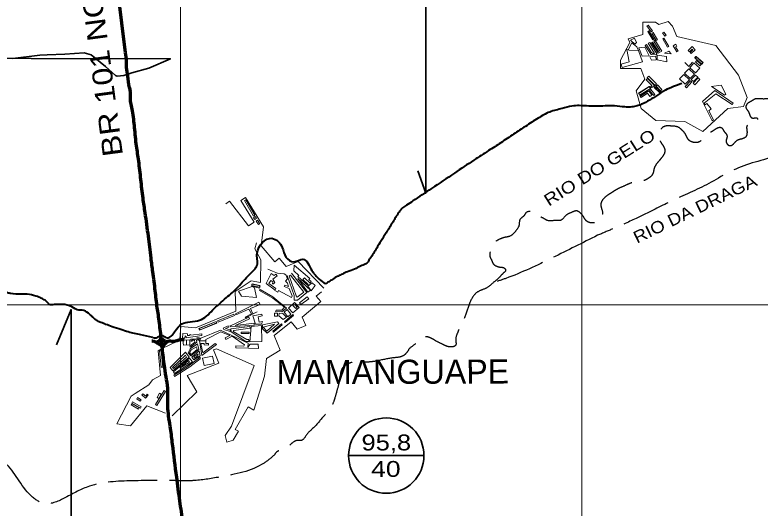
# Model space of a CAD drawing. Extents: x 0 to 1682, y 0 to 1188.
# Drawn here: x 1499.4 to 1617.7, y 586 to 664.3 of the extents above; entities that cross this region are included whole.
import ezdxf
from ezdxf.enums import TextEntityAlignment as Align

# ---------------------------------------------------------------- set-up
doc = ezdxf.new("R2010")
doc.units = 0
doc.header["$LTSCALE"] = 1.3
doc.linetypes.add('DOT_DASHED', pattern=[7.7, 5, -1.2, 0.3, -1.2])
doc.linetypes.add('LONG_DASHED', pattern=[7.5, 6, -1.5])
for name, color, linetype, lineweight in [('1', 7, 'DOT_DASHED', 13), ('3', 7, 'Continuous', 35), ('4', 7, 'Continuous', 13), ('5', 7, 'LONG_DASHED', 25), ('6', 7, 'Continuous', 40), ('63', 7, 'Continuous', 25), ('8', 7, 'Continuous', 35), ('9', 7, 'Continuous', 40)]:
    doc.layers.add(name, color=color, linetype=linetype, lineweight=lineweight)

msp = doc.modelspace()

# ---------------------------------------------------------------- linework, layer by layer
at = {"layer": '1', "linetype": 'Continuous'}
for p, q in [((1612.301, 651.769), (1612.093, 651.595)), ((1525.103, 612.432), (1523.013, 611.428)), ((1526.676, 611.907), (1526.165, 611.897)), ((1526.676, 611.898), (1526.666, 612.683))]:
    msp.add_line(p, q, dxfattribs=at)
for points in [[(1615.089, 649.802), (1612.587, 649.456), (1608.64, 645.821), (1605.76, 647.404), (1601.16, 647.559), (1598.854, 649.449), (1598.067, 652.257), (1599.415, 654.123), (1598.801, 655.815), (1595.554, 655.839), (1595.563, 657.125), (1597.064, 659.941), (1596.791, 660.515), (1599.123, 661.2), (1599.117, 663.197), (1601.115, 663.203), (1601.655, 662.799), (1603.142, 663.311), (1603.821, 662.534), (1603.821, 662.534), (1604.536, 660.911), (1610.696, 659.473), (1614.33, 654.743), (1615.66, 651.192)], [(1599.739, 662.576), (1600.421, 661.632), (1600.629, 661.782), (1599.947, 662.726)], [(1599.904, 661.72), (1600.706, 660.392), (1600.875, 660.494), (1600.074, 661.822)], [(1600.54, 661.441), (1601.223, 660.245), (1601.43, 660.364), (1600.747, 661.559)], [(1602.223, 661.46), (1602.594, 660.944), (1602.797, 661.09), (1602.427, 661.607)], [(1597.133, 660.307), (1597.782, 660.62), (1598.094, 659.971), (1597.858, 659.689)], [(1601.045, 660.363), (1600.839, 660.185), (1601.818, 658.636), (1601.604, 658.501), (1600.653, 660.005), (1600.506, 659.912), (1601.567, 658.234), (1602.11, 658.577)], [(1602.27, 660.529), (1603.057, 659.187), (1603.249, 659.3), (1602.463, 660.642)], [(1598.48, 659.084), (1599.03, 657.785), (1600.137, 657.848), (1599.41, 659.205)], [(1601.318, 658.176), (1600.205, 659.976), (1599.955, 659.822), (1600.958, 658.199), (1600.683, 658.204), (1600.46, 658.41), (1599.689, 659.62), (1599.482, 659.488), (1600.419, 658.018), (1601.244, 657.984)], [(1604.516, 658.475), (1603.94, 659.399), (1604.357, 659.659), (1604.528, 659.385), (1604.311, 659.25), (1604.725, 658.585)], [(1606.809, 658.219), (1606.644, 658.383), (1607.053, 658.794), (1606.939, 658.907), (1606.518, 658.484), (1606.319, 658.682), (1606.941, 659.308), (1607.446, 658.805)], [(1595.832, 655.973), (1595.682, 656.534), (1596.928, 656.865), (1596.576, 658.827), (1596.96, 658.725), (1598.422, 658.656), (1599.077, 656.884)], [(1602.931, 656.895), (1601.409, 657.216), (1601.392, 657.925), (1602.884, 657.723)], [(1603.621, 658.124), (1602.572, 658.269), (1603.236, 658.596)], [(1600.212, 657.671), (1600.464, 657.139), (1601.232, 657.215), (1601.176, 657.781)], [(1607.483, 655.119), (1606.557, 655.947), (1607.235, 656.705), (1608.161, 655.877)], [(1608.488, 656.524), (1607.358, 657.516), (1607.56, 657.745), (1608.69, 656.754)], [(1608.446, 656.511), (1607.366, 657.554), (1607.554, 657.75), (1608.634, 656.706)], [(1607.478, 656.89), (1608.176, 656.226), (1608.371, 656.43), (1607.672, 657.094)], [(1605.753, 655.067), (1606.64, 654.223), (1607.322, 654.94), (1606.435, 655.784)], [(1601.306, 653.368), (1600.054, 654.613), (1599.812, 654.37), (1601.063, 653.124)], [(1606.529, 654.014), (1605.603, 654.892), (1604.936, 654.188), (1605.861, 653.31)], [(1607.15, 653.739), (1607.822, 654.423), (1607.466, 654.772), (1606.795, 654.088)], [(1608.19, 654.071), (1607.355, 653.246), (1607.09, 653.515), (1607.925, 654.34)], [(1600.536, 652.824), (1600.388, 652.971), (1600.535, 653.119), (1599.625, 654.025), (1599.838, 654.24), (1600.956, 653.128)], [(1601.215, 653.003), (1601.926, 652.281), (1602.157, 652.508), (1601.446, 653.231)], [(1606.666, 653.877), (1605.833, 652.958), (1606.055, 652.757), (1606.888, 653.676)], [(1598.432, 651.901), (1600.128, 652.982), (1600.33, 652.666), (1598.608, 651.568)], [(1598.457, 651.827), (1600.181, 652.97), (1600.367, 652.69), (1598.643, 651.547)], [(1598.858, 651.193), (1599.875, 651.89), (1600.242, 651.356), (1600.557, 651.572), (1600.061, 652.294), (1598.705, 651.363)], [(1600.183, 652.29), (1600.835, 651.509), (1601.043, 651.682), (1600.391, 652.464)], [(1601.808, 651.955), (1600.905, 652.795), (1601.04, 652.94), (1601.943, 652.1)], [(1536.092, 634.97), (1537.501, 632.513), (1537.278, 632.385), (1535.869, 634.842)], [(1537.766, 632.026), (1537.562, 632.289), (1537.299, 632.085), (1537.502, 631.822)], [(1537.93, 631.721), (1538.297, 631.153), (1538.089, 631.018), (1537.721, 631.586)], [(1546.225, 622.472), (1543.741, 624.579), (1543.682, 623.684), (1544.497, 622.934), (1544.341, 622.764), (1545.844, 621.381), (1545.983, 621.532), (1545.138, 622.31), (1545.372, 622.565), (1546.268, 621.74), (1546.471, 621.96), (1546.098, 622.304)], [(1544.06, 619.699), (1542.933, 622.889), (1543.182, 622.977), (1545.277, 620.272), (1544.253, 619.479)], [(1544.356, 622.466), (1545.947, 620.315), (1546.332, 620.6)], [(1538.292, 621.324), (1537.097, 621.602), (1537.039, 621.352), (1538.234, 621.074)], [(1537.05, 621.253), (1537.05, 621.554), (1538.331, 621.322), (1538.263, 620.95)], [(1546.613, 621.761), (1545.904, 621.23), (1546.435, 620.521), (1547.082, 621.335)], [(1537.775, 619.463), (1535.371, 619.65), (1534.923, 620.464), (1537.091, 621.169), (1537.479, 620.956)], [(1540.877, 617.419), (1541.792, 617.422), (1542.235, 617.894), (1540.388, 619.327), (1538.268, 620.55), (1538.352, 620.697), (1540.384, 619.525), (1542.549, 617.738), (1541.819, 617.186), (1540.773, 617.196)], [(1544.795, 618.319), (1544.591, 618.582), (1545.836, 619.545), (1546.081, 619.229)], [(1535.981, 616.306), (1535.981, 616.306), (1536.959, 616.871), (1536.537, 617.601), (1534.516, 616.694), (1534.446, 616.85), (1538.169, 618.68), (1538.349, 618.313), (1536.839, 617.721), (1537.176, 616.861), (1537.901, 617.146), (1536.02, 616.188)], [(1544.558, 617.853), (1543.799, 618.671), (1542.834, 617.775), (1543.554, 617)], [(1544.025, 617.678), (1543.528, 618.161), (1543.875, 618.311), (1544.248, 617.927)], [(1531.686, 615.517), (1534.257, 616.579), (1534.167, 616.796), (1531.596, 615.734)], [(1538.558, 615.214), (1537.604, 615.212), (1537.208, 616.518), (1538.632, 616.81), (1538.691, 616.519), (1538.028, 616.383), (1538.205, 615.522), (1538.71, 615.626)], [(1540.617, 616.475), (1540.616, 616.96), (1541.1, 616.961), (1541.101, 616.477)], [(1542.021, 615.933), (1541.336, 616.552), (1541.372, 616.962), (1541.945, 616.912), (1542.516, 616.344)], [(1542.727, 616.395), (1542.141, 617.113), (1542.639, 617.519), (1543.22, 616.805)], [(1542.345, 615.45), (1543.669, 616.596), (1543.545, 616.739), (1542.221, 615.592)], [(1531.476, 615.376), (1528.741, 614.267), (1528.638, 614.521), (1531.373, 615.63)], [(1531.438, 615.395), (1528.803, 614.314), (1528.716, 614.527), (1531.35, 615.607)], [(1533.56, 614.914), (1536.551, 616.305), (1536.671, 616.048), (1534.407, 614.996), (1537.42, 615.371), (1537.38, 615.066), (1533.622, 614.759), (1533.602, 615.012)], [(1538.725, 614.445), (1539.484, 613.789), (1541.34, 615.297), (1541.124, 615.564), (1538.735, 615.103)], [(1538.062, 612.022), (1536.775, 612.018), (1536.402, 611.549), (1536.447, 612.181), (1532.041, 614.277), (1528.932, 613.002), (1528.652, 612.556), (1529.706, 612.513), (1529.706, 612.513), (1529.705, 612.794), (1529.705, 612.794), (1532.135, 613.973), (1533.564, 613.414), (1532.793, 613.014), (1532.914, 612.782), (1533.906, 613.297), (1535.886, 611.945), (1535.736, 611.726), (1534.505, 611.754), (1534.499, 611.448), (1536.476, 611.403), (1538.108, 611.367)], [(1533.585, 614.018), (1533.585, 614.29), (1532.867, 614.521), (1533.37, 614.755), (1533.281, 614.945), (1532.506, 614.584), (1532.611, 614.36)], [(1536.536, 612.456), (1536.535, 612.766), (1536.224, 612.765), (1534.089, 614.059), (1534.19, 614.226), (1536.743, 614.571), (1536.703, 614.862), (1533.704, 614.456), (1533.768, 613.981), (1536.071, 612.435)], [(1536.728, 612.376), (1536.944, 614.818), (1538.589, 615.006), (1538.596, 612.463)], [(1539.396, 614.112), (1538.811, 614.743), (1540.621, 615.184)], [(1540.599, 614.053), (1541.849, 615.113), (1541.718, 615.268), (1540.341, 614.101), (1540.494, 613.921)], [(1529.103, 613.407), (1529.102, 613.655), (1527.331, 613.443), (1527.316, 613.562), (1527.114, 613.538), (1527.127, 613.426), (1526.835, 613.391), (1526.8, 613.683), (1526.069, 613.72), (1526.032, 612.989), (1526.418, 612.97), (1526.438, 613.357), (1526.614, 613.194), (1526.615, 613.062)], [(1528.438, 612.613), (1528.28, 613.058), (1528.725, 613.06)], [(1535.318, 613.935), (1536.605, 613.939), (1536.606, 613.705), (1535.319, 613.701)], [(1526.165, 611.897), (1526.08, 612.664), (1527.185, 612.7), (1527.211, 611.899)], [(1528.629, 611.189), (1528.418, 612.061), (1527.241, 611.283), (1526.899, 610.655), (1527.368, 610.152)], [(1527.373, 612.511), (1527.372, 612.821), (1528.167, 612.824), (1528.303, 612.328), (1527.303, 611.559), (1527.174, 611.727), (1527.967, 612.336), (1527.93, 612.647), (1527.566, 612.647), (1527.566, 612.495), (1527.357, 612.495)], [(1531.415, 611.97), (1531.217, 612.151), (1529.268, 610.652), (1528.95, 612.153), (1529.469, 612.13), (1529.459, 611.899), (1530.128, 611.87), (1530.14, 612.139), (1529.734, 612.158), (1529.752, 612.563), (1528.697, 612.61), (1529.096, 610.231)], [(1522.621, 608.368), (1522.38, 610.961), (1522.638, 610.985), (1522.879, 608.392)], [(1524.477, 607.771), (1524.082, 608.311), (1526.494, 610.74), (1527.061, 609.979)], [(1528.371, 611.176), (1527.391, 610.411), (1527.143, 610.728), (1527.377, 611.148), (1528.247, 611.63)], [(1528.804, 610.169), (1528.654, 610.967), (1527.479, 609.981), (1527.845, 609.544)], [(1524.574, 608.153), (1524.438, 608.349), (1526.508, 610.297), (1526.644, 609.966)], [(1527.148, 609.808), (1527.591, 609.207), (1524.761, 607.367), (1524.596, 607.621)], [(1528.83, 609.69), (1528.829, 609.992), (1526.685, 608.368), (1524.639, 607.084), (1524.763, 606.886), (1527.196, 608.413)], [(1525.593, 608.217), (1527.137, 609.181), (1526.966, 609.455)], [(1528.46, 610.156), (1527.97, 609.785), (1527.812, 609.995), (1528.508, 610.521)], [(1529.463, 608.631), (1529.221, 609.81), (1530.804, 610.136), (1531.047, 608.957)], [(1521.739, 602.44), (1523.097, 604.652), (1523.306, 604.523), (1521.948, 602.312)], [(1518.755, 603.335), (1519.323, 603.001), (1519.443, 603.206), (1518.876, 603.54)], [(1519.579, 603.988), (1520.156, 603.433), (1520.567, 603.954), (1520.423, 604.067), (1520.176, 603.754), (1519.699, 604.131)], [(1522.009, 603.555), (1522.385, 604.229), (1522.622, 604.097), (1522.246, 603.423)], [(1517.897, 602.387), (1519.012, 601.718), (1519.125, 601.906), (1518.01, 602.575)], [(1519.452, 602.055), (1518.084, 602.85), (1517.961, 602.638), (1519.328, 601.843)]]:
    msp.add_lwpolyline(points, close=True, dxfattribs=at)
for points in [[(1596.787, 658.771), (1597.385, 659.894), (1598.17, 659.261), (1598.422, 658.656)], [(1605.804, 656.764), (1606.396, 656.148), (1606.982, 656.806)], [(1612.301, 651.769), (1611.534, 653.19), (1610.009, 652.977), (1610.009, 652.977), (1611.051, 652.286), (1612.093, 651.595), (1612.093, 651.595)], [(1613.476, 650.338), (1610.533, 652.324), (1608.572, 650.56), (1610.102, 647.52), (1610.353, 647.646), (1609.573, 649.093)], [(1609.573, 649.093), (1609.965, 649.409), (1609.292, 650.245), (1609.037, 650.04), (1608.832, 650.294), (1610.712, 651.809), (1613.293, 650.075), (1613.476, 650.338)], [(1548.444, 620.922), (1544.365, 625.156), (1542.496, 624.351), (1541.345, 625.696), (1540.672, 625.12), (1538.494, 627.664), (1538.91, 630.684), (1536.027, 635.321), (1535.272, 634.851), (1537.415, 631.405), (1536.525, 630.851), (1533.459, 634.739), (1532.921, 634.314)], [(1537.77, 628.108), (1537.498, 627.183), (1538.477, 625.413), (1538.413, 621.816), (1536.915, 622.112), (1534.4, 620.406), (1534.509, 617.284), (1528.112, 614.637), (1525.744, 614.829), (1525.59, 612.936)], [(1543.32, 619.433), (1543.437, 619.729), (1542.937, 620.875), (1542.191, 621.181), (1542.288, 621.417), (1542.876, 621.176), (1542.71, 621.715), (1542.378, 622.057), (1542.72, 622.389), (1542.411, 623.027), (1542.186, 623.18), (1541.121, 623.331), (1540.293, 623.601), (1539.595, 623.954)], [(1543.32, 619.433), (1541.277, 620.531), (1541.146, 620.289), (1540.677, 620.541), (1540.862, 620.885), (1539.739, 621.684), (1540.07, 622.15), (1540.366, 621.94), (1540.329, 621.627), (1540.476, 621.61), (1540.671, 621.841), (1540.386, 622.372), (1541.034, 622.882), (1540.822, 623.151), (1540.552, 622.939), (1540.112, 623.233), (1539.326, 621.683), (1540.734, 620.612)], [(1543.778, 619.007), (1543.775, 619.739), (1542.628, 622.929)], [(1543.778, 619.007), (1544.306, 619.009), (1545.744, 620.233), (1543.332, 623.314)], [(1524.39, 600.63), (1524.39, 600.63), (1526.353, 602.532), (1528.316, 604.434), (1526.739, 607.074), (1531.767, 609.009), (1530.953, 611.123), (1531.437, 611.309), (1537.383, 608.661), (1533.828, 599.016), (1532.775, 597.509), (1533.051, 596.485), (1534.075, 596.761), (1534.889, 598.199), (1534.402, 598.474), (1536.437, 602.069), (1537.364, 601.544), (1539.06, 606.923), (1539.359, 609.76), (1541.539, 611.099), (1540.577, 613.385), (1543.3, 615.58), (1544.231, 614.425), (1545.589, 614.971), (1545.042, 616.329), (1547.966, 618.805), (1547.252, 619.649), (1548.096, 620.363)], [(1522.664, 611.278), (1522.142, 610.952), (1522.527, 607.036), (1521.283, 606.359), (1520.663, 605.584), (1518.499, 604.18), (1518.182, 603.975), (1517.866, 603.77), (1515.622, 599.357), (1517.791, 599.039), (1520.373, 602.24), (1523.342, 601.051)]]:
    msp.add_lwpolyline(points, dxfattribs=at)
at = {"layer": '3'}
msp.add_lwpolyline([(1499.06, 657.432), (1503.369, 657.961), (1504.554, 657.971), (1507.355, 658.093), (1510.404, 658.333), (1511.495, 657.98), (1513.79, 656.158), (1515.388, 654.695), (1515.663, 654.593), (1516.727, 654.706), (1517.964, 655.145), (1520.678, 655.849), (1524.117, 657.365), (1391.313, 657.655)], dxfattribs=at)
msp.add_lwpolyline([(1499.06, 657.432), (1503.369, 657.961), (1504.554, 657.971), (1507.355, 658.093), (1510.404, 658.333), (1511.495, 657.98), (1513.79, 656.158), (1515.388, 654.695), (1515.663, 654.593), (1516.727, 654.706), (1517.964, 655.145), (1520.678, 655.849), (1524.117, 657.365), (1391.313, 657.655)], dxfattribs=at)
at = {"layer": '4', "lineweight": 70}
msp.add_line((1516.973, 658.327), (1514.176, 681.178), dxfattribs=at)
for points in [[(1522.848, 611.382), (1522.521, 614.052), (1522.189, 616.707), (1522.016, 617.803), (1521.7, 620.519), (1521.305, 623.499), (1521.037, 625.706), (1520.608, 629.164), (1520.096, 632.896), (1519.755, 635.208), (1519.412, 638.189), (1519.069, 641.114), (1518.728, 643.51), (1518.413, 646.435), (1518.071, 649.109), (1517.759, 651.17), (1517.756, 652.185), (1517.619, 652.783), (1517.32, 654.601), (1517.141, 656.004), (1517.138, 657.019), (1516.973, 658.327)], [(1521.846, 612.338), (1522.358, 612.583), (1522.646, 613.035)], [(1523.543, 612.393), (1522.989, 612.665), (1522.614, 612.982)], [(1522.844, 611.319), (1522.682, 611.721), (1522.126, 612.151), (1521.693, 612.397), (1521.146, 612.516)], [(1526.591, 578.894), (1526.079, 583.694), (1525.607, 587.106), (1525.099, 590.91), (1524.442, 596.14), (1524.128, 598.618), (1523.709, 601.771), (1523.701, 604.536), (1523.199, 608.242), (1522.864, 610.924), (1522.862, 611.505), (1523.021, 611.83), (1523.467, 612.325), (1523.714, 612.496), (1524.562, 612.498), (1525.826, 612.78), (1526.289, 612.781)]]:
    msp.add_spline(points, degree=3, dxfattribs=at)
at = {"layer": '5'}
for points in [[(1630.321, 659.326), (1629.513, 656.919), (1626.666, 651.968), (1623.932, 646.96), (1622.871, 645.103), (1621.978, 643.472), (1615.59, 640.532), (1609.203, 637.367), (1603.208, 634.541), (1598.277, 632.11), (1594.355, 630.357), (1591.939, 629.323)], [(1632.944, 659.876), (1632.249, 660.14), (1631.333, 659.901), (1630.019, 659.157), (1629.074, 658.68), (1628.452, 658.915), (1627.196, 658.69), (1625.529, 657.53), (1623.995, 656.356), (1623.48, 655.644), (1623.481, 655.171), (1623.099, 654.385), (1623.103, 653.053), (1623.313, 651.929), (1622.813, 650.98), (1622.43, 650.727), (1621.331, 650.914), (1620.662, 651.12), (1620.082, 650.987), (1619.206, 650.984), (1618.046, 650.981), (1616.972, 650.978), (1616.273, 650.603), (1615.792, 650.305), (1615.541, 649.998), (1615.542, 649.45), (1615.839, 649.034), (1616.049, 648.541), (1616.324, 648.049), (1616.653, 647.94), (1617.255, 647.942), (1617.256, 647.547), (1616.884, 647.436), (1616.348, 647.314), (1615.911, 647.006), (1615.638, 646.665), (1615.64, 645.975), (1615.642, 645.449), (1615.468, 644.966), (1614.933, 644.657)], [(1614.933, 644.657), (1614.058, 644.365), (1613.474, 643.813), (1613.133, 643.543), (1612.815, 643.542), (1612.534, 643.834), (1612.386, 644.201), (1612.517, 645.203), (1612.186, 645.642), (1611.929, 646.045), (1611.659, 646.362), (1610.984, 646.36), (1610.102, 645.827), (1609.399, 645.401), (1608.93, 644.938), (1608.443, 644.438), (1607.955, 644.117), (1607.025, 644.114), (1606.545, 644.348), (1606.196, 644.761), (1605.874, 645.39), (1605.318, 646.048), (1604.708, 646.515), (1603.678, 646.677), (1602.728, 646.674), (1602.2, 646.422), (1601.837, 645.877), (1601.719, 645.026), (1601.892, 644.282), (1602.395, 643.461), (1602.619, 642.718), (1602.463, 642.181), (1601.986, 641.507), (1601.602, 641.034), (1601.184, 640.518), (1600.913, 639.943), (1600.765, 639.279), (1600.488, 638.782), (1600.06, 638.423), (1599.476, 638.087), (1598.558, 637.862), (1597.39, 637.685), (1596.378, 637.257), (1595.072, 636.664), (1594.286, 636.185), (1593.474, 635.645), (1592.696, 634.898), (1592.439, 634.221), (1592.684, 633.129), (1592.445, 632.036), (1591.927, 631.497), (1591.201, 631.287), (1590.265, 631.527), (1589.656, 632.34)], [(1589.702, 632.279), (1589.132, 632.935), (1588.592, 633.199), (1587.877, 632.991), (1586.869, 632.457), (1586.047, 631.68), (1585.371, 631.678), (1583.969, 631.673), (1583.36, 632.005), (1582.672, 632.386), (1582.047, 632.89), (1580.545, 632.886), (1580.203, 632.38), (1579.63, 631.874), (1579.462, 630.955), (1578.87, 629.934), (1578.015, 629.185), (1577.274, 629.003), (1576.402, 628.716), (1575.504, 628.107), (1575.112, 627.389), (1574.875, 626.735), (1574.878, 625.825), (1575.081, 625.431), (1575.257, 624.972), (1575.57, 624.596), (1576.039, 624.367), (1576.498, 624.268), (1577.095, 624.132), (1577.335, 623.755), (1577.015, 623.359), (1576.301, 622.603), (1575.413, 621.856)], [(1591.932, 629.328), (1584.756, 625.749), (1577.365, 622.478), (1575.322, 621.784)], [(1575.413, 621.856), (1574.26, 620.936), (1572.872, 620.319), (1571.652, 618.64), (1570.787, 616.208), (1569.663, 613.798), (1569.407, 612.665), (1569.409, 611.887), (1568.185, 611.647), (1567.312, 612.022), (1566.179, 612.585), (1565.636, 612.913), (1564.645, 613.194), (1563.422, 612.435), (1562.035, 611.346)], [(1562.035, 611.346), (1561.407, 610.442), (1560.887, 610.102), (1559.678, 609.877), (1557.169, 609.426), (1555.881, 609.214), (1554.424, 609.21), (1553.215, 609.206), (1552.097, 608.786), (1551.488, 608.342), (1551.089, 607.232), (1550.746, 605.427), (1550.258, 603.667), (1549.804, 602.365), (1549.194, 601.42), (1548.373, 600.492), (1546.69, 598.628), (1545.7, 597.604), (1544.911, 596.742), (1544.24, 596.74), (1543.289, 596.186), (1542.392, 595.525), (1541.36, 595.119), (1540.797, 594.728), (1540.637, 594.445)], [(1540.637, 594.445), (1538.976, 593.143), (1531.925, 590.923), (1527.681, 590.354), (1525.485, 590.347), (1518.055, 590.325), (1511.231, 589.463), (1507.437, 587.669), (1504.175, 586.709), (1501.975, 587.95), (1497.804, 593.227), (1493.465, 595.293), (1488.773, 596.111), (1485.973, 596.103), (1484.215, 595.353), (1483.136, 594.131), (1480.835, 594.124), (1477.854, 594.838), (1474.326, 597.854), (1470.621, 599.65), (1467.101, 599.639), (1464.755, 599.632), (1460.602, 600.297), (1456.723, 599.699), (1455.146, 599.107), (1451.442, 594.713)]]:
    msp.add_spline(points, degree=3, dxfattribs=at)
at = {"layer": '6'}
msp.add_line((1502.809, 619.661), (1502.716, 619.681), dxfattribs=at)
for points in [[(1502.716, 619.681), (1501.363, 619.958), (1500.312, 619.955), (1498.778, 620.084), (1498.251, 620.192), (1497.803, 620.428), (1497.449, 620.771), (1496.676, 621.6), (1495.843, 622.466), (1495.101, 623.228), (1494.5, 623.863), (1493.971, 624.389), (1492.527, 625.84), (1491.47, 626.881), (1490.059, 628.306), (1488.397, 629.971), (1487.28, 631.114), (1485.938, 632.491), (1485.341, 633.089), (1484.834, 633.638), (1484.053, 634.118), (1483.095, 634.69), (1482.292, 635.098), (1481.886, 635.59), (1481.289, 636.278), (1480.27, 636.833), (1479.287, 637.143), (1478.262, 637.414), (1477.204, 637.41), (1476.321, 636.999), (1475.673, 636.578), (1475.254, 636.421), (1474.759, 636.599), (1474.145, 636.822), (1473.436, 637.065), (1473.166, 637.241), (1472.779, 637.819), (1472.098, 638.463), (1471.201, 639.063), (1470.162, 639.553), (1469.437, 639.551), (1468.833, 639.876), (1468.169, 640.143), (1467.488, 640.348), (1467.153, 640.598), (1466.719, 641.062), (1466.352, 641.369), (1466.103, 641.765), (1465.875, 642.36), (1465.55, 642.931), (1465.096, 643.504), (1464.733, 643.976), (1464.343, 644.566), (1463.868, 645.108), (1463.365, 645.662), (1462.769, 646.184), (1462.073, 646.739), (1461.275, 647.232), (1460.56, 647.571), (1460.289, 647.751), (1460.184, 647.975), (1460.182, 648.709), (1459.394, 649.262), (1458.875, 649.703), (1458.053, 650.533), (1457.51, 651.107), (1456.748, 651.714), (1455.473, 651.71), (1454.276, 651.496), (1452.627, 651.491), (1451.545, 651.171), (1449.344, 650.91), (1447.851, 650.717), (1446.508, 650.523), (1445.422, 650.339), (1444.558, 650.336), (1443.944, 650.555), (1442.831, 651.196), (1442.204, 651.631), (1441.643, 652.452), (1440.554, 652.943), (1439.935, 653.523), (1439.253, 654.187), (1438.15, 654.704), (1436.826, 654.896), (1435.947, 654.541), (1435.459, 653.978), (1434.955, 653.658), (1434.02, 653.232), (1433.081, 652.678), (1432.342, 652.312)], [(1605.302, 653.425), (1602.69, 652.355), (1600.171, 650.788), (1598.887, 650.128), (1598.23, 649.895), (1597.349, 649.718), (1596.263, 649.715), (1594.633, 649.878), (1593.141, 649.874), (1590.172, 649.865), (1587.863, 649.858), (1586.311, 649.468), (1584.336, 648.908), (1582.481, 647.92), (1580.481, 646.628), (1578.601, 645.399), (1576.549, 644.021), (1574.627, 642.772), (1572.293, 641.262), (1569.196, 639.195), (1565.569, 636.759), (1562.62, 634.778), (1561.598, 634.098), (1560.943, 633.666), (1560.596, 633.289), (1560.218, 632.729), (1559.736, 631.97), (1559.449, 631.472), (1558.546, 630.008), (1556.999, 627.524), (1555.915, 625.781), (1555.55, 625.239), (1555.395, 624.983), (1555.125, 624.786), (1554.296, 624.422), (1553.331, 623.964), (1552.223, 623.539), (1551.403, 623.165), (1550.716, 622.859), (1549.834, 622.313), (1549.256, 621.944), (1548.701, 621.59)], [(1521.328, 613.09), (1522.016, 613.092), (1522.466, 613.425), (1523.208, 613.197), (1523.569, 613.038), (1524.778, 614.014), (1525.894, 615.239), (1528.734, 615.822), (1530.795, 617.409), (1532.999, 619.427), (1534.831, 621.099), (1536.691, 623.144), (1537.863, 624.584), (1537.858, 626.481), (1540.233, 628.844), (1541.873, 627.383), (1542.447, 625.873), (1543.715, 625.13), (1545.119, 625.516), (1546.581, 623.732), (1547.73, 622.364), (1548.696, 621.604)], [(1521.328, 613.09), (1519.433, 613.512), (1517.405, 613.968), (1516.246, 614.335), (1514.838, 614.801), (1513.868, 615.173), (1513.056, 615.483), (1512.514, 615.718), (1512.044, 616.064), (1511.653, 616.439), (1511.074, 616.961), (1510.08, 617.435), (1509.581, 617.433), (1508.432, 617.944), (1506.939, 618.342), (1506.403, 618.341), (1505.621, 618.338), (1504.872, 618.336), (1504.702, 618.524), (1504.203, 618.997), (1503.6, 619.361), (1502.809, 619.661)]]:
    msp.add_spline(points, degree=3, dxfattribs=at)
at = {"layer": '63', "lineweight": 13}
for p, q in [((1525.723, 427.142), (1525.723, 783.93)), ((1589.435, 427.142), (1589.435, 783.93)), ((1640.404, 618.279), (952.314, 618.279))]:
    msp.add_line(p, q, dxfattribs=at)
at = {"layer": '8'}
for points in [[(1577.007, 696.204), (1564.657, 696.204), (1564.657, 635.994), (1563.391, 639.56)], [(1503.457, 571.743), (1508.337, 571.743), (1508.337, 617.515), (1506.002, 611.908)]]:
    msp.add_lwpolyline(points, dxfattribs=at)
at = {"layer": '9', "lineweight": 35}
msp.add_line((1552.392, 594.33), (1564.363, 594.33), dxfattribs=at)
msp.add_circle((1558.377, 594.33), 5.985, dxfattribs=at)

# ---------------------------------------------------------------- texts
at = {"layer": '5'}
for s, rotation, width, p in [('RIO DO GELO', 32.342, 1.2, (1584.181, 633.864)), ('RIO DA DRAGA', 25.865, 1.15, (1598.183, 627.979))]:
    msp.add_text(s, height=1.911, rotation=rotation, dxfattribs=dict(at, width=width)).set_placement(p)
at = {"layer": '8', "width": 1.2}
msp.add_text('BR 101 NORTE', height=3.186, rotation=97.529, dxfattribs=at).set_placement((1516.58, 642.056))
at = {"layer": '9'}
msp.add_text('MAMANGUAPE', height=3.823, rotation=0.17, dxfattribs=at).set_placement((1540.968, 605.676))
for s, width, p in [('95,8', 1.2, (1558.387, 595.15)), ('40', 1.25, (1558.313, 590.947))]:
    msp.add_text(s, height=2.52, rotation=0.17, dxfattribs=dict(at, width=width)).set_placement(p, align=Align.CENTER)

doc.saveas('drawing.dxf')
